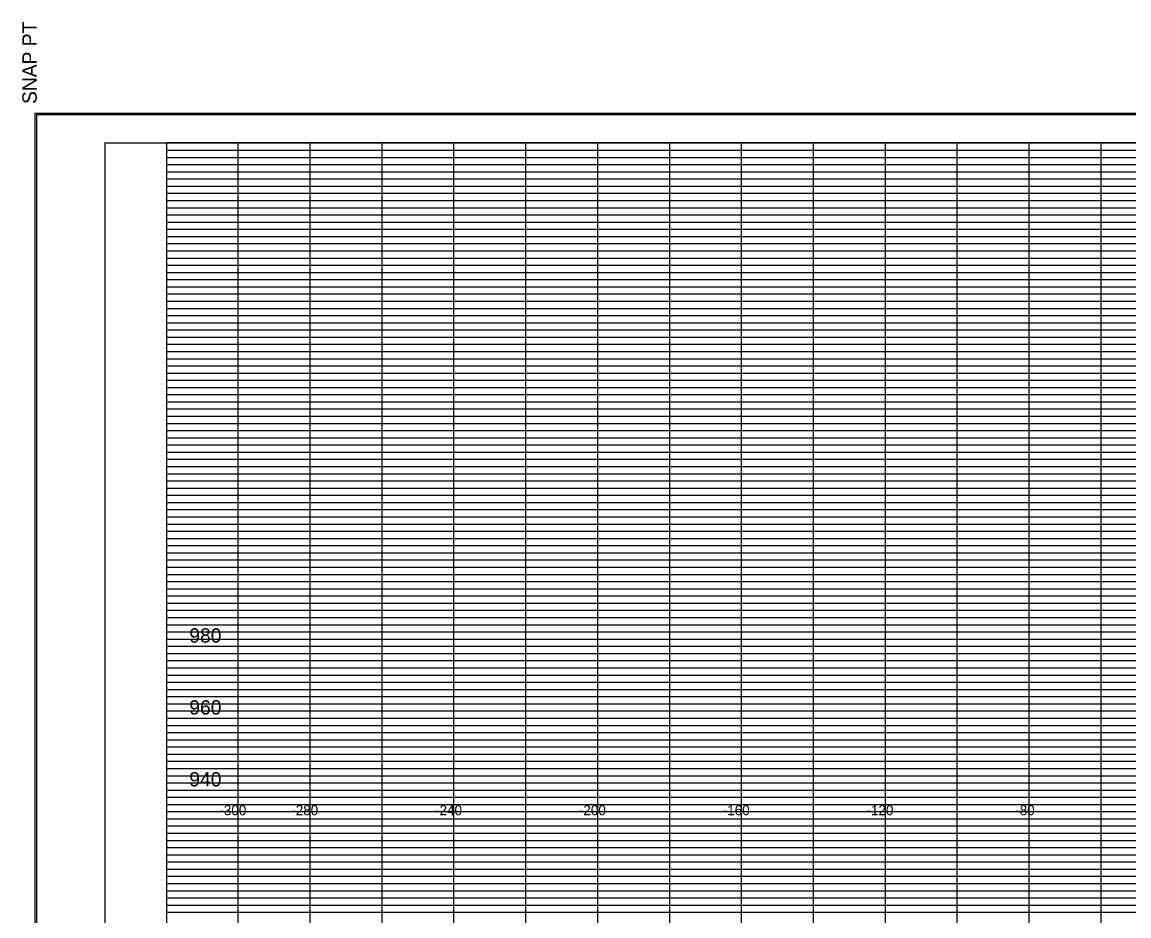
# Model space of a CAD drawing. Extents: x 2313580 to 2322968, y 282099 to 303247.
# Drawn here: x 2318423.6 to 2318731.4, y 287792.7 to 288041.3 of the extents above; entities that cross this region are included whole.
import ezdxf

# ---------------------------------------------------------------- set-up
doc = ezdxf.new("R2010")
doc.units = 0
for name, color, linetype in [('DESIGN - SHEET - Corner Text', 7, 'Continuous'), ('DESIGN - SHEET - Light Grid', 7, 'Continuous'), ('DESIGN - SHEET - Linework', 7, 'Continuous'), ('DESIGN - SHEET - Plot Shape', 7, 'Continuous'), ('DESIGN - TYPICAL - Text', 7, 'Continuous')]:
    doc.layers.add(name, color=color, linetype=linetype)

msp = doc.modelspace()

# ---------------------------------------------------------------- linework, layer by layer
at = {"layer": 'DESIGN - SHEET - Light Grid'}
for p, q in [((2318463.68, 288005.67), (2318623.68, 288005.67)), ((2318623.68, 288005.67), (2318783.68, 288005.67)), ((2318463.68, 288003.67), (2318623.68, 288003.67)), ((2318463.68, 288001.67), (2318623.68, 288001.67)), ((2318623.68, 288003.67), (2318783.68, 288003.67)), ((2318623.68, 288001.67), (2318783.68, 288001.67)), ((2318463.68, 287999.67), (2318623.68, 287999.67)), ((2318463.68, 287997.67), (2318623.68, 287997.67)), ((2318623.68, 287999.67), (2318783.68, 287999.67)), ((2318623.68, 287997.67), (2318783.68, 287997.67)), ((2318463.68, 287995.67), (2318623.68, 287995.67)), ((2318623.68, 287995.67), (2318783.68, 287995.67)), ((2318463.68, 287993.67), (2318623.68, 287993.67)), ((2318463.68, 287991.67), (2318623.68, 287991.67)), ((2318623.68, 287993.67), (2318783.68, 287993.67)), ((2318623.68, 287991.67), (2318783.68, 287991.67)), ((2318463.68, 287989.67), (2318623.68, 287989.67)), ((2318623.68, 287989.67), (2318783.68, 287989.67)), ((2318463.68, 287985.67), (2318623.68, 287985.67)), ((2318623.68, 287985.67), (2318783.68, 287985.67)), ((2318463.68, 287983.67), (2318623.68, 287983.67)), ((2318623.68, 287983.67), (2318783.68, 287983.67)), ((2318463.68, 287981.67), (2318623.68, 287981.67)), ((2318463.68, 287979.67), (2318623.68, 287979.67)), ((2318623.68, 287981.67), (2318783.68, 287981.67)), ((2318623.68, 287979.67), (2318783.68, 287979.67)), ((2318463.68, 287977.67), (2318623.68, 287977.67)), ((2318623.68, 287977.67), (2318783.68, 287977.67)), ((2318463.68, 287975.67), (2318623.68, 287975.67)), ((2318463.68, 287973.67), (2318623.68, 287973.67)), ((2318623.68, 287975.67), (2318783.68, 287975.67)), ((2318623.68, 287973.67), (2318783.68, 287973.67)), ((2318463.68, 287971.67), (2318623.68, 287971.67)), ((2318623.68, 287971.67), (2318783.68, 287971.67)), ((2318463.68, 287969.67), (2318623.68, 287969.67)), ((2318623.68, 287969.67), (2318783.68, 287969.67)), ((2318463.68, 287965.67), (2318623.68, 287965.67)), ((2318463.68, 287963.67), (2318623.68, 287963.67)), ((2318623.68, 287965.67), (2318783.68, 287965.67)), ((2318623.68, 287963.67), (2318783.68, 287963.67)), ((2318463.68, 287961.67), (2318623.68, 287961.67)), ((2318623.68, 287961.67), (2318783.68, 287961.67)), ((2318463.68, 287959.67), (2318623.68, 287959.67)), ((2318463.68, 287957.67), (2318623.68, 287957.67)), ((2318623.68, 287959.67), (2318783.68, 287959.67)), ((2318623.68, 287957.67), (2318783.68, 287957.67)), ((2318463.68, 287955.67), (2318623.68, 287955.67)), ((2318623.68, 287955.67), (2318783.68, 287955.67)), ((2318463.68, 287953.67), (2318623.68, 287953.67)), ((2318463.68, 287951.67), (2318623.68, 287951.67)), ((2318623.68, 287953.67), (2318783.68, 287953.67)), ((2318623.68, 287951.67), (2318783.68, 287951.67)), ((2318463.68, 287949.67), (2318623.68, 287949.67)), ((2318623.68, 287949.67), (2318783.68, 287949.67)), ((2318463.68, 287945.67), (2318623.68, 287945.67)), ((2318623.68, 287945.67), (2318783.68, 287945.67)), ((2318463.68, 287943.67), (2318623.68, 287943.67)), ((2318623.68, 287943.67), (2318783.68, 287943.67)), ((2318463.68, 287941.67), (2318623.68, 287941.67)), ((2318463.68, 287939.67), (2318623.68, 287939.67)), ((2318623.68, 287941.67), (2318783.68, 287941.67)), ((2318623.68, 287939.67), (2318783.68, 287939.67)), ((2318463.68, 287937.67), (2318623.68, 287937.67)), ((2318623.68, 287937.67), (2318783.68, 287937.67)), ((2318463.68, 287935.67), (2318623.68, 287935.67)), ((2318463.68, 287933.67), (2318623.68, 287933.67)), ((2318623.68, 287935.67), (2318783.68, 287935.67)), ((2318623.68, 287933.67), (2318783.68, 287933.67)), ((2318463.68, 287931.67), (2318623.68, 287931.67)), ((2318623.68, 287931.67), (2318783.68, 287931.67)), ((2318463.68, 287929.67), (2318623.68, 287929.67)), ((2318623.68, 287929.67), (2318783.68, 287929.67)), ((2318463.68, 287925.67), (2318623.68, 287925.67)), ((2318463.68, 287923.67), (2318623.68, 287923.67)), ((2318623.68, 287925.67), (2318783.68, 287925.67)), ((2318623.68, 287923.67), (2318783.68, 287923.67)), ((2318463.68, 287921.67), (2318623.68, 287921.67)), ((2318623.68, 287921.67), (2318783.68, 287921.67)), ((2318463.68, 287919.67), (2318623.68, 287919.67)), ((2318463.68, 287917.67), (2318623.68, 287917.67)), ((2318623.68, 287919.67), (2318783.68, 287919.67)), ((2318623.68, 287917.67), (2318783.68, 287917.67)), ((2318463.68, 287915.67), (2318623.68, 287915.67)), ((2318623.68, 287915.67), (2318783.68, 287915.67)), ((2318463.68, 287913.67), (2318623.68, 287913.67)), ((2318463.68, 287911.67), (2318623.68, 287911.67)), ((2318623.68, 287913.67), (2318783.68, 287913.67)), ((2318623.68, 287911.67), (2318783.68, 287911.67)), ((2318463.68, 287909.67), (2318623.68, 287909.67)), ((2318623.68, 287909.67), (2318783.68, 287909.67)), ((2318463.68, 287905.67), (2318623.68, 287905.67)), ((2318623.68, 287905.67), (2318783.68, 287905.67)), ((2318463.68, 287903.67), (2318623.68, 287903.67)), ((2318623.68, 287903.67), (2318783.68, 287903.67)), ((2318463.68, 287901.67), (2318623.68, 287901.67)), ((2318463.68, 287899.67), (2318623.68, 287899.67)), ((2318623.68, 287901.67), (2318783.68, 287901.67)), ((2318623.68, 287899.67), (2318783.68, 287899.67)), ((2318463.68, 287897.67), (2318623.68, 287897.67)), ((2318623.68, 287897.67), (2318783.68, 287897.67)), ((2318463.68, 287895.67), (2318623.68, 287895.67)), ((2318463.68, 287893.67), (2318623.68, 287893.67)), ((2318623.68, 287895.67), (2318783.68, 287895.67)), ((2318623.68, 287893.67), (2318783.68, 287893.67)), ((2318463.68, 287891.67), (2318623.68, 287891.67)), ((2318623.68, 287891.67), (2318783.68, 287891.67)), ((2318463.68, 287889.67), (2318623.68, 287889.67)), ((2318623.68, 287889.67), (2318783.68, 287889.67)), ((2318463.68, 287885.67), (2318623.68, 287885.67)), ((2318463.68, 287883.67), (2318623.68, 287883.67)), ((2318623.68, 287885.67), (2318783.68, 287885.67)), ((2318623.68, 287883.67), (2318783.68, 287883.67)), ((2318463.68, 287881.67), (2318623.68, 287881.67)), ((2318623.68, 287881.67), (2318783.68, 287881.67)), ((2318463.68, 287879.67), (2318623.68, 287879.67)), ((2318463.68, 287877.67), (2318623.68, 287877.67)), ((2318623.68, 287879.67), (2318783.68, 287879.67)), ((2318623.68, 287877.67), (2318783.68, 287877.67)), ((2318463.68, 287875.67), (2318623.68, 287875.67)), ((2318623.68, 287875.67), (2318783.68, 287875.67)), ((2318463.68, 287873.67), (2318623.68, 287873.67)), ((2318463.68, 287871.67), (2318623.68, 287871.67)), ((2318623.68, 287873.67), (2318783.68, 287873.67)), ((2318623.68, 287871.67), (2318783.68, 287871.67)), ((2318463.68, 287869.67), (2318623.68, 287869.67)), ((2318623.68, 287869.67), (2318783.68, 287869.67)), ((2318463.68, 287865.67), (2318623.68, 287865.67)), ((2318623.68, 287865.67), (2318783.68, 287865.67)), ((2318463.68, 287863.67), (2318623.68, 287863.67)), ((2318623.68, 287863.67), (2318783.68, 287863.67)), ((2318463.68, 287861.67), (2318623.68, 287861.67)), ((2318463.68, 287859.67), (2318623.68, 287859.67)), ((2318623.68, 287861.67), (2318783.68, 287861.67)), ((2318623.68, 287859.67), (2318783.68, 287859.67)), ((2318463.68, 287857.67), (2318623.68, 287857.67)), ((2318623.68, 287857.67), (2318783.68, 287857.67)), ((2318463.68, 287855.67), (2318623.68, 287855.67)), ((2318463.68, 287853.67), (2318623.68, 287853.67)), ((2318623.68, 287855.67), (2318783.68, 287855.67)), ((2318623.68, 287853.67), (2318783.68, 287853.67)), ((2318463.68, 287851.67), (2318623.68, 287851.67)), ((2318623.68, 287851.67), (2318783.68, 287851.67)), ((2318463.68, 287849.67), (2318623.68, 287849.67)), ((2318623.68, 287849.67), (2318783.68, 287849.67)), ((2318463.68, 287845.67), (2318623.68, 287845.67)), ((2318463.68, 287843.67), (2318623.68, 287843.67)), ((2318623.68, 287845.67), (2318783.68, 287845.67)), ((2318623.68, 287843.67), (2318783.68, 287843.67)), ((2318463.68, 287841.67), (2318623.68, 287841.67)), ((2318623.68, 287841.67), (2318783.68, 287841.67)), ((2318463.68, 287839.67), (2318623.68, 287839.67)), ((2318463.68, 287837.67), (2318623.68, 287837.67)), ((2318623.68, 287839.67), (2318783.68, 287839.67)), ((2318623.68, 287837.67), (2318783.68, 287837.67)), ((2318463.68, 287835.67), (2318623.68, 287835.67)), ((2318623.68, 287835.67), (2318783.68, 287835.67)), ((2318463.68, 287833.67), (2318623.68, 287833.67)), ((2318463.68, 287831.67), (2318623.68, 287831.67)), ((2318623.68, 287833.67), (2318783.68, 287833.67)), ((2318623.68, 287831.67), (2318783.68, 287831.67)), ((2318463.68, 287829.67), (2318623.68, 287829.67)), ((2318623.68, 287829.67), (2318783.68, 287829.67)), ((2318463.68, 287825.67), (2318623.68, 287825.67)), ((2318623.68, 287825.67), (2318783.68, 287825.67)), ((2318463.68, 287823.67), (2318623.68, 287823.67)), ((2318623.68, 287823.67), (2318783.68, 287823.67)), ((2318463.68, 287821.67), (2318623.68, 287821.67)), ((2318463.68, 287819.67), (2318623.68, 287819.67)), ((2318623.68, 287821.67), (2318783.68, 287821.67)), ((2318623.68, 287819.67), (2318783.68, 287819.67)), ((2318463.68, 287817.67), (2318623.68, 287817.67)), ((2318623.68, 287817.67), (2318783.68, 287817.67)), ((2318463.68, 287815.67), (2318623.68, 287815.67)), ((2318463.68, 287813.67), (2318623.68, 287813.67)), ((2318623.68, 287815.67), (2318783.68, 287815.67)), ((2318623.68, 287813.67), (2318783.68, 287813.67)), ((2318463.68, 287811.67), (2318623.68, 287811.67)), ((2318623.68, 287811.67), (2318783.68, 287811.67)), ((2318463.68, 287809.67), (2318623.68, 287809.67)), ((2318623.68, 287809.67), (2318783.68, 287809.67)), ((2318463.68, 287805.67), (2318623.68, 287805.67)), ((2318463.68, 287803.67), (2318623.68, 287803.67)), ((2318623.68, 287805.67), (2318783.68, 287805.67)), ((2318623.68, 287803.67), (2318783.68, 287803.67)), ((2318463.68, 287801.67), (2318623.68, 287801.67)), ((2318623.68, 287801.67), (2318783.68, 287801.67)), ((2318463.68, 287799.67), (2318623.68, 287799.67)), ((2318463.68, 287797.67), (2318623.68, 287797.67)), ((2318623.68, 287799.67), (2318783.68, 287799.67)), ((2318623.68, 287797.67), (2318783.68, 287797.67)), ((2318463.68, 287795.67), (2318623.68, 287795.67)), ((2318623.68, 287795.67), (2318783.68, 287795.67)), ((2318463.68, 287793.67), (2318623.68, 287793.67)), ((2318623.68, 287793.67), (2318783.68, 287793.67))]:
    msp.add_line(p, q, dxfattribs=at)
at = {"layer": 'DESIGN - SHEET - Linework'}
for p, q in [((2318427.22, 287579.39), (2318427.22, 288015.95)), ((2318427.22, 288015.95), (2319108.02, 288015.95)), ((2318483.68, 287587.67), (2318483.68, 288007.67)), ((2318503.68, 287587.67), (2318503.68, 288007.67)), ((2318523.68, 287587.67), (2318523.68, 288007.67)), ((2318543.68, 287587.67), (2318543.68, 288007.67)), ((2318563.68, 287587.67), (2318563.68, 288007.67)), ((2318583.68, 287587.67), (2318583.68, 288007.67)), ((2318603.68, 287587.67), (2318603.68, 288007.67)), ((2318623.68, 287587.67), (2318623.68, 288007.67)), ((2318643.68, 287587.67), (2318643.68, 288007.67)), ((2318663.68, 287587.67), (2318663.68, 288007.67)), ((2318683.68, 287587.67), (2318683.68, 288007.67)), ((2318703.68, 287587.67), (2318703.68, 288007.67)), ((2318723.68, 287587.67), (2318723.68, 288007.67)), ((2318463.68, 287987.67), (2319023.68, 287987.67)), ((2318463.68, 287967.67), (2319103.68, 287967.67)), ((2318463.68, 287947.67), (2319103.68, 287947.67)), ((2318463.68, 287927.67), (2319103.68, 287927.67)), ((2318463.68, 287907.67), (2319103.68, 287907.67)), ((2318463.68, 287887.67), (2319103.68, 287887.67)), ((2318463.68, 287867.67), (2319103.68, 287867.67)), ((2318463.68, 287847.67), (2319103.68, 287847.67)), ((2318463.68, 287827.67), (2319103.68, 287827.67)), ((2318463.68, 287807.67), (2319103.68, 287807.67))]:
    msp.add_line(p, q, dxfattribs=at)
msp.add_lwpolyline([(2318463.68, 288007.67), (2318463.68, 287587.67), (2319103.68, 287587.67), (2319103.68, 288007.67), (2318463.68, 288007.67)], dxfattribs=at)
at = {"layer": 'DESIGN - SHEET - Plot Shape'}
for points in [[(2318427.62, 288015.55), (2319107.62, 288015.55), (2319107.62, 287579.79), (2318427.62, 287579.79)], [(2318446.68, 288007.67), (2319103.68, 288007.67), (2319103.68, 287582.67), (2318446.68, 287582.67)]]:
    msp.add_lwpolyline(points, close=True, dxfattribs=at)

# ---------------------------------------------------------------- texts
at = {"layer": 'DESIGN - SHEET - Corner Text'}
msp.add_text('  SNAP PT', height=4, rotation=90, dxfattribs=at).set_placement((2318427.62, 288015.55))
at = {"layer": 'DESIGN - SHEET - Linework'}
msp.add_text('-', height=0.0001, dxfattribs=at).set_placement((2318483.68, 287827.67))
at = {"layer": 'DESIGN - TYPICAL - Text'}
for s, height, p in [('980', 4, (2318470.06, 287868.67)), ('960', 4, (2318470.06, 287848.67)), ('940', 4, (2318470.06, 287828.67)), ('-300', 2.8, (2318478.42, 287820.67)), ('-280', 2.8, (2318498.42, 287820.67)), ('-240', 2.8, (2318538.42, 287820.67)), ('-200', 2.8, (2318578.42, 287820.67)), ('-160', 2.8, (2318618.42, 287820.67)), ('-120', 2.8, (2318658.42, 287820.67)), ('-80', 2.8, (2318699.79, 287820.67))]:
    msp.add_text(s, height=height, dxfattribs=at).set_placement(p)

doc.saveas('drawing.dxf')
